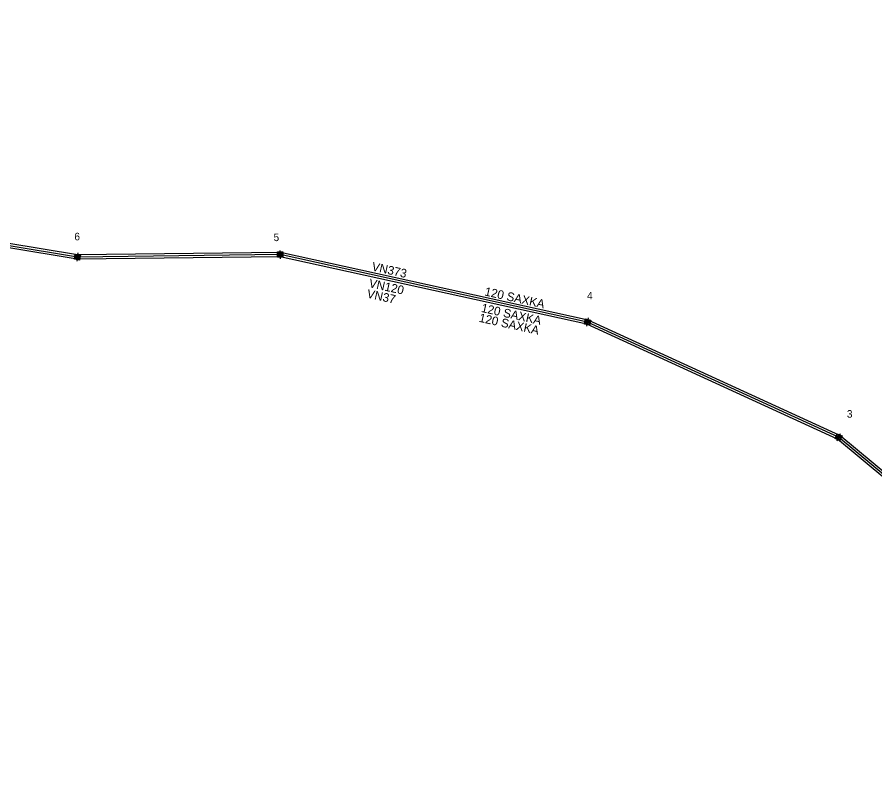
# Model space of a CAD drawing. Extents: x -540879 to -537255, y -1184046 to -1180016.
# Drawn here: x -537831.1 to -537632.5, y -1180650.1 to -1180475.4 of the extents above; entities that cross this region are included whole.
import ezdxf

# ---------------------------------------------------------------- set-up
doc = ezdxf.new("R2010")
doc.units = 0
for name, color, linetype in [('Vrstva 13', 7, 'Continuous'), ('Vrstva 14', 7, 'Continuous'), ('Vrstva 2', 7, 'Continuous'), ('Vrstva 50', 7, 'Continuous'), ('Vrstva 51', 7, 'Continuous')]:
    doc.layers.add(name, color=color, linetype=linetype)

# ---------------------------------------------------------------- blocks, each defined once
blk = doc.blocks.new('VN470')
at = {"layer": 'Vrstva 2'}
for points in [[(-1.23, 1.22), (1.23, 1.22)], [(-1.23, -1.23), (-1.23, 1.22)], [(-0.92, 0.9), (0.92, 0.9)], [(-0.92, -0.95), (-0.92, 0.9)], [(-0.61, 0.61), (0.61, 0.61)], [(-0.61, -0.62), (-0.61, 0.61)], [(-0.31, -0.27), (-0.31, 0.34)], [(-0.31, 0.34), (0.31, 0.34)], [(0, 1.22), (0, 1.97)], [(0.31, 0.34), (0.31, -0.27)], [(0.61, 0.61), (0.61, -0.62)], [(0.92, 0.9), (0.92, -0.95)], [(1.23, 1.22), (1.23, -1.23)], [(1.23, -1.23), (-1.23, -1.23)], [(0.92, -0.95), (-0.92, -0.95)], [(0.61, -0.62), (-0.61, -0.62)], [(0.31, -0.27), (-0.31, -0.27)], [(0, -1.23), (0, -1.98)]]:
    blk.add_lwpolyline(points, dxfattribs=at)

msp = doc.modelspace()

# ---------------------------------------------------------------- linework, layer by layer
at = {"layer": 'Vrstva 50'}
for points in [[(-537549.42, -1180647.98), (-537594.82, -1180610.26), (-537640.66, -1180572.18), (-537698.89, -1180545.49), (-537770.12, -1180529.84), (-537817.09, -1180530.41), (-537899.91, -1180516.71), (-537967.43, -1180502.43), (-538028.9, -1180486.5), (-538083.27, -1180475.39)], [(-537548.92, -1180649.05), (-537595.14, -1180610.65), (-537640.93, -1180572.61), (-537699.05, -1180545.96), (-537770.17, -1180530.35), (-537817.13, -1180530.91), (-537900, -1180517.2), (-537967.54, -1180502.92), (-538029.01, -1180486.99), (-538083.27, -1180475.98)], [(-537548.49, -1180650.05), (-537595.46, -1180611.03), (-537641.2, -1180573.04), (-537699.21, -1180546.44), (-537770.22, -1180530.85), (-537817.17, -1180531.41), (-537900.09, -1180517.69), (-537967.65, -1180503.41), (-538029.12, -1180487.48), (-538083.26, -1180476.62)]]:
    msp.add_lwpolyline(points, dxfattribs=at)

# ---------------------------------------------------------------- block references
at = {"layer": 'Vrstva 13', "xscale": 0.5}
for p, yscale, rotation in [((-537817.13, -1180530.91), 0.49999999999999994, -9.409577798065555), ((-537770.17, -1180530.35), 0.5, -0.002599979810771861), ((-537699.05, -1180545.96), 0.5000000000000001, -12.382436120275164), ((-537640.93, -1180572.61), 0.5, -24.63292779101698)]:
    msp.add_blockref('VN470', p, dxfattribs=dict(at, yscale=yscale, rotation=rotation))

# ---------------------------------------------------------------- texts
at = {"layer": 'Vrstva 14'}
for s, p in [('6', (-537817.85, -1180527.04)), ('5', (-537771.73, -1180527.22)), ('4', (-537699.16, -1180540.73)), ('3', (-537639.01, -1180568.09))]:
    msp.add_text(s, height=1.75, dxfattribs=at).set_placement(p)
at = {"layer": 'Vrstva 51'}
for s, p in [('VN373', (-537749.12, -1180534.01)), ('VN120', (-537749.79, -1180537.86)), ('120 SAXKA', (-537723, -1180539.78)), ('VN37', (-537750.26, -1180540.29)), ('120 SAXKA', (-537723.79, -1180543.59)), ('120 SAXKA', (-537724.3, -1180545.87))]:
    msp.add_text(s, height=2, rotation=347.615, dxfattribs=at).set_placement(p)

doc.saveas('drawing.dxf')
